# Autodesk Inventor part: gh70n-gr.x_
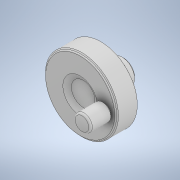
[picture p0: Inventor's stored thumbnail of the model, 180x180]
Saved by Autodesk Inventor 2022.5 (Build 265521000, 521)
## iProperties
Created: 2023-06
Part Number: gh70n-gr.x_
Material: Generic
Document SubType Name: Modeling
Designer: ImaoCorp
Density: 1 g/cm^3
Appearance: Default
Sending System: SOLIDWORKS 2021-2021301
MC: AMD64
MC_MODEL: Intel64 Family 6 Model 60 Stepping 3, GenuineIntel
OS: Windows_NT
FRU: Parasolid Version 32.1, build 255,  1- 1-2021
FORMAT: text
GUISE: transmit
KEY: gh70n-gr
FILE: gh70n-gr.x_t
DATE: Thu Jun 15 16:07:52 2023
Author: ImaoCorp
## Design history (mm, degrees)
feature "Base1"
node "ソリッド1"
